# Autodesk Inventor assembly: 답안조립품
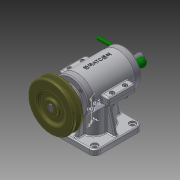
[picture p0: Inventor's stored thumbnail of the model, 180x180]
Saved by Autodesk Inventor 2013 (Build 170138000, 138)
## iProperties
Created: 2015-12
Part Number: 답안조립품
Document SubType Name: Assembly
Designer: Administrator
Mass: 1960.54 g
Surface Area: 1487.03 cm^2
Volume: 472.444 cm^3
Density: 4.14978 g/cm^3
Author: Administrator
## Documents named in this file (19)
- C:\Documents and Settings\Administrator\바탕 화면\351208V1002\답안조립품.iam
- C:\Documents and Settings\Administrator\바탕 화면\351208V1002\V-벨트풀리.ipt
- C:\Documents and Settings\Administrator\바탕 화면\351208V1002\가변스프링.ipt
- C:\Documents and Settings\Administrator\바탕 화면\351208V1002\너트 M4.ipt
- C:\Documents and Settings\Administrator\바탕 화면\351208V1002\뒤커버.ipt
- C:\Documents and Settings\Administrator\바탕 화면\351208V1002\레바.ipt
- C:\Documents and Settings\Administrator\바탕 화면\351208V1002\멈춤나사 M3x8.ipt
- C:\Documents and Settings\Administrator\바탕 화면\351208V1002\베어링 6201.ipt
- C:\Documents and Settings\Administrator\바탕 화면\351208V1002\베어링 6202.ipt
- C:\Documents and Settings\Administrator\바탕 화면\351208V1002\본체.ipt
- C:\Documents and Settings\Administrator\바탕 화면\351208V1002\본체커버.ipt
- C:\Documents and Settings\Administrator\바탕 화면\351208V1002\볼트 M3x0.5x8.ipt
- C:\Documents and Settings\Administrator\바탕 화면\351208V1002\볼트 M4 x 16.ipt
- C:\Documents and Settings\Administrator\바탕 화면\351208V1002\슬라이드.ipt
- C:\Documents and Settings\Administrator\바탕 화면\351208V1002\앞커버.ipt
- C:\Documents and Settings\Administrator\바탕 화면\351208V1002\오일실 12 22 7.ipt
- C:\Documents and Settings\Administrator\바탕 화면\351208V1002\와셔 ST 4-100.ipt
- C:\Documents and Settings\Administrator\바탕 화면\351208V1002\키 4 x 4 x 18.ipt
- C:\Documents and Settings\Administrator\바탕 화면\351208V1002\편심축.ipt
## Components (14 placed, 5 different names)
1. V-벨트풀리:1 — 플러쉬:1
2. 가변스프링:1
3. ISO 4032 M4:1 — 각도:5
4. ISO 4762 M4 x 16:1
5. ISO 7091 ST 4 - 100 HV:1
6. ISO 4762 M4 x 16:2
7. ISO 4762 M4 x 16:3
8. ISO 4762 M4 x 16:4
9. ISO 7091 ST 4 - 100 HV:2
10. ISO 7091 ST 4 - 100 HV:3
11. ISO 7091 ST 4 - 100 HV:4
12. ISO 4032 M4:2 — 각도:4
13. ISO 4032 M4:4 — 각도:3
14. ISO 4032 M4:5 — 각도:2
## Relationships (5: Angle 4, Flush 1)
- 플러쉬:1 [Flush]: V-벨트풀리:1
- 각도:2 [Angle]: ISO 4032 M4:5
- 각도:3 [Angle]: ISO 4032 M4:4
- 각도:4 [Angle]: ISO 4032 M4:2
- 각도:5 [Angle]: ISO 4032 M4:1
